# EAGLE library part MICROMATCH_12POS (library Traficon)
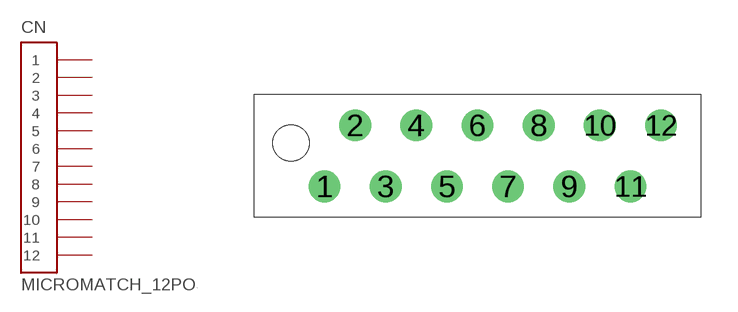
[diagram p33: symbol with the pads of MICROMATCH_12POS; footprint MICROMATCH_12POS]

Designator prefix CN

## MICROMATCH_12POS  [MICROMATCH_12POS]
1  1
2  2
3  3
4  4
5  5
6  6
7  7
8  8
9  9
10  10
11  11
12  12

## Footprint MICROMATCH_12POS (pad centres in mm)
drill 0.813 round: 1 -2.54,-2.54; 2 -1.27,0; 3 0,-2.54; 4 1.27,0; 5 2.54,-2.54; 6 3.81,0; 7 5.08,-2.54; 8 6.35,0; 9 7.62,-2.54; 10 8.89,0; 11 10.16,-2.54; 12 11.43,0
hole 1.5 at -3.94,-0.74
